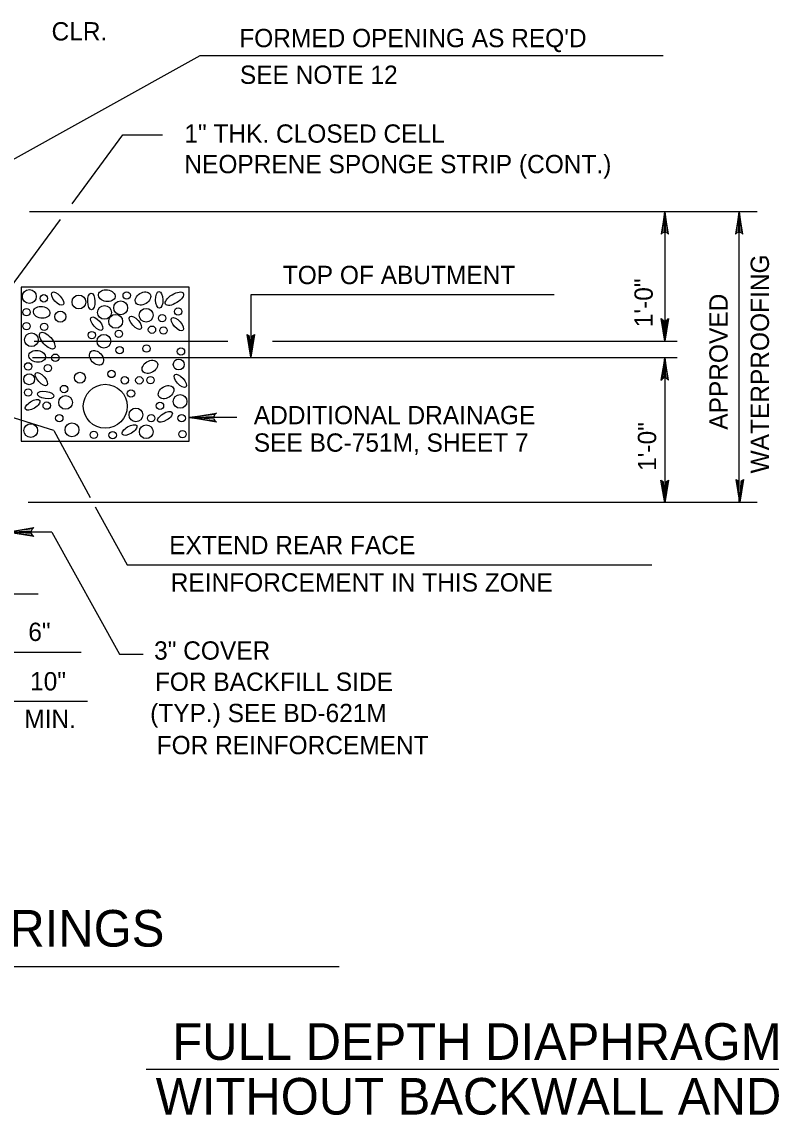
# Model space of a CAD drawing. Extents: x 640009 to 641706, y 298547 to 299735.
# Drawn here: x 640241.3 to 640364.1, y 298840.1 to 299019.2 of the extents above; entities that cross this region are included whole.
import ezdxf

# ---------------------------------------------------------------- set-up
doc = ezdxf.new("R2010")
doc.units = 0
doc.layers.add('1', color=7, linetype='Continuous')

msp = doc.modelspace()

# ---------------------------------------------------------------- linework, layer by layer
at = {"layer": '1'}
for p, q in [((640219.04, 298985.1), (640270.52, 299013.67)), ((640270.52, 299013.67), (640346.41, 299013.67)), ((640249.51, 298989.36), (640257.85, 299000.68)), ((640257.85, 299000.68), (640264.33, 299000.68)), ((640242.54, 298988.1), (640361.79, 298988.1)), ((640346.65, 298988.1), (640346.65, 298966.85)), ((640358.83, 298940.47), (640358.83, 298988.1)), ((640233.17, 298967.22), (640247.62, 298986.81)), ((640328.54, 298974.47), (640278.79, 298974.47)), ((640278.79, 298974.47), (640278.79, 298964.22)), ((640243.29, 298966.85), (640275.01, 298966.85)), ((640282.36, 298966.85), (640348.67, 298966.85)), ((640243.04, 298964.22), (640348.67, 298964.22)), ((640346.65, 298964.22), (640346.65, 298940.47)), ((640246.54, 298952.22), (640234.67, 298955.97)), ((640276.51, 298954.35), (640268.7, 298954.35)), ((640246.54, 298952.22), (640252.46, 298941.25)), ((640242.28, 298940.47), (640361.79, 298940.47)), ((640253.28, 298939.73), (640258.54, 298930.22)), ((640246.18, 298935.6), (640238.79, 298935.6)), ((640246.18, 298935.6), (640257.26, 298915.59)), ((640258.54, 298930.22), (640344.54, 298930.22)), ((640217.42, 298925.47), (640243.92, 298925.47)), ((640251.01, 298915.85), (640226.42, 298915.85)), ((640257.26, 298915.59), (640261.17, 298915.59)), ((640252.04, 298907.85), (640219.29, 298907.85)), ((640161, 298864.4), (640293.29, 298864.4)), ((640261.67, 298847.62), (640460.34, 298847.62))]:
    msp.add_line(p, q, dxfattribs=at)
for points in [[(640347.1, 298984.56), (640346.84, 298984.7), (640346.65, 298988.1), (640347.1, 298984.56), (640347.26, 298984.38), (640346.65, 298988.1), (640346.49, 298984.7), (640346.23, 298984.57), (640346.65, 298988.1), (640346.05, 298984.38), (640346.23, 298984.57)], [(640359.28, 298984.56), (640359.02, 298984.7), (640358.83, 298988.1), (640359.28, 298984.56), (640359.43, 298984.38), (640358.83, 298988.1), (640358.67, 298984.7), (640358.41, 298984.57), (640358.83, 298988.1), (640358.23, 298984.38), (640358.41, 298984.57)], [(640347.1, 298970.39), (640346.84, 298970.24), (640346.65, 298966.85), (640347.1, 298970.39), (640347.26, 298970.56), (640346.65, 298966.85), (640346.49, 298970.24), (640346.23, 298970.37), (640346.65, 298966.85), (640346.05, 298970.56), (640346.23, 298970.37)], [(640279.23, 298967.8), (640278.97, 298967.65), (640278.78, 298964.26), (640279.23, 298967.8), (640279.38, 298967.97), (640278.78, 298964.26), (640278.61, 298967.65), (640278.36, 298967.78), (640278.78, 298964.26), (640278.18, 298967.97), (640278.36, 298967.78)], [(640347.09, 298960.65), (640346.82, 298960.79), (640346.64, 298964.18), (640347.09, 298960.65), (640347.24, 298960.47), (640346.64, 298964.18), (640346.47, 298960.79), (640346.22, 298960.66), (640346.64, 298964.18), (640346.03, 298960.47), (640346.22, 298960.66)], [(640272.95, 298953.81), (640272.77, 298954.12), (640268.7, 298954.35), (640272.95, 298953.81), (640273.16, 298953.62), (640268.7, 298954.35), (640272.77, 298954.54), (640272.93, 298954.85), (640268.7, 298954.35), (640273.16, 298955.07), (640272.93, 298954.85)], [(640347.09, 298943.92), (640346.82, 298943.78), (640346.64, 298940.38), (640347.09, 298943.92), (640347.24, 298944.1), (640346.64, 298940.38), (640346.47, 298943.78), (640346.22, 298943.91), (640346.64, 298940.38), (640346.03, 298944.1), (640346.22, 298943.91)], [(640359.38, 298944.05), (640359.12, 298943.9), (640358.93, 298940.51), (640359.38, 298944.05), (640359.54, 298944.22), (640358.93, 298940.51), (640358.77, 298943.9), (640358.51, 298944.03), (640358.93, 298940.51), (640358.33, 298944.22), (640358.51, 298944.03)], [(640243.04, 298935.07), (640242.86, 298935.38), (640238.79, 298935.6), (640243.04, 298935.07), (640243.25, 298934.88), (640238.79, 298935.6), (640242.86, 298935.8), (640243.02, 298936.11), (640238.79, 298935.6), (640243.25, 298936.33), (640243.02, 298936.11)]]:
    msp.add_lwpolyline(points, dxfattribs=at)
msp.add_lwpolyline([(640268.7, 298975.7), (640241.17, 298975.7), (640241.17, 298950.51), (640268.7, 298950.51)], close=True, dxfattribs=at)
for centre, radius in [((640242.5, 298974.19), 1.13), ((640244.88, 298973.89), 0.605), ((640250.63, 298973.29), 1.13), ((640258.46, 298974.37), 0.605), ((640254.82, 298971.59), 1.13), ((640257.47, 298972.33), 1.13), ((640242.03, 298971.61), 0.605), ((640247.57, 298970.89), 0.9), ((640256.65, 298970.12), 1.13), ((640261.65, 298971.11), 1.13), ((640264.26, 298970.65), 0.605), ((640266.88, 298971.72), 0.605), ((640242.03, 298969.33), 0.605), ((640244.93, 298969.22), 0.605), ((640262.6, 298968.75), 0.605), ((640264.5, 298968.63), 0.605), ((640242.84, 298967.11), 1.13), ((640252.74, 298967.87), 0.605), ((640254.72, 298966.86), 1.13), ((640257.18, 298968.08), 0.605), ((640257.3, 298965.4), 0.605), ((640261.7, 298965.66), 0.605), ((640267.35, 298965.19), 0.605), ((640246.76, 298964.16), 0.605), ((640266.99, 298963.05), 0.9), ((640242.3, 298962.74), 0.605), ((640245.54, 298962.44), 0.605), ((640250.79, 298960.88), 0.9), ((640255.97, 298961.5), 0.605), ((640242.47, 298960.63), 0.9), ((640258.14, 298960.46), 0.605), ((640260.53, 298960.46), 0.605), ((640262.35, 298960.49), 0.605), ((640242.3, 298958.46), 0.605), ((640248.19, 298959.03), 0.605), ((640254.94, 298956.21), 3.6), ((640259.16, 298958.29), 0.605), ((640245.35, 298956.31), 0.605), ((640248.45, 298956.84), 1.13), ((640263.91, 298956.27), 0.605), ((640267.2, 298957), 1.13), ((640247.41, 298954.25), 0.605), ((640259.97, 298954.79), 1.13), ((640262.48, 298954.25), 0.605), ((640267.47, 298954.25), 0.605), ((640242.73, 298952.22), 1.13), ((640249.49, 298952.34), 1.13), ((640261.67, 298952.03), 1.13), ((640253.06, 298951.53), 0.605), ((640256.16, 298951.47), 0.605), ((640267.59, 298951.64), 0.605)]:
    msp.add_circle(centre, radius, dxfattribs=at)
for centre, major_axis, ratio in [((640247.13, 298973.84), (0.91, -1.02), 0.438009), ((640252.66, 298973.39), (0.04, -1.37), 0.438009), ((640255.19, 298974.33), (1.36, -0.2), 0.696126), ((640261.12, 298973.86), (1.17, 0.72), 0.696126), ((640263.79, 298973.63), (0.04, -1.37), 0.438009), ((640266.28, 298973.83), (1.46, 0.9), 0.438009), ((640244.52, 298971.6), (1.36, -0.2), 0.696126), ((640253.55, 298969.74), (0.91, -1.02), 0.438009), ((640259.89, 298969.88), (0.91, -1.02), 0.438009), ((640266.76, 298969.65), (0.91, -1.02), 0.438009), ((640245.44, 298966.96), (1.14, -1.28), 0.438009), ((640243.79, 298964.39), (1.36, -0.2), 0.696126), ((640253.51, 298964.14), (0.91, -1.02), 0.696126), ((640262.26, 298962.68), (1.17, 0.72), 0.696126), ((640244.48, 298960.65), (0.91, -1.02), 0.438009), ((640267.24, 298960.38), (0.91, -1.02), 0.438009), ((640245.17, 298958.05), (1.36, -0.2), 0.438009), ((640264.91, 298958.52), (1.17, 0.72), 0.696126), ((640243.03, 298956.43), (1.17, 0.72), 0.438009), ((640264.73, 298954.47), (1.17, 0.72), 0.438009), ((640258.93, 298952.31), (1.17, 0.72), 0.438009)]:
    msp.add_ellipse(centre, major_axis=major_axis, ratio=ratio, dxfattribs=at)

# ---------------------------------------------------------------- texts
for s, height, p in [('CLR.', 3, (640246.14, 299016.14)), ("FORMED OPENING AS REQ'D", 3, (640276.9, 299015.04)), ('SEE NOTE 12', 3, (640277.01, 299009.03)), ('1" THK. CLOSED CELL', 3, (640267.91, 298999.39)), ('NEOPRENE SPONGE STRIP (CONT.)', 3, (640267.91, 298994.39)), ('TOP OF ABUTMENT', 3, (640284.04, 298976.22)), ('ADDITIONAL DRAINAGE', 3, (640279.29, 298953.26)), ('SEE BC-751M, SHEET 7', 3, (640279.29, 298948.76)), ('EXTEND REAR FACE', 3, (640265.42, 298931.97)), ('REINFORCEMENT IN THIS ZONE', 3, (640265.67, 298925.85)), ('6"', 3, (640242.33, 298917.75)), ('3" COVER', 3, (640262.95, 298914.69)), ('10"', 3, (640242.62, 298909.65)), ('FOR BACKFILL SIDE', 3, (640263.08, 298909.57)), ('MIN.', 3, (640241.67, 298903.48)), ('(TYP.) SEE BD-621M', 3, (640262.3, 298904.45)), ('FOR REINFORCEMENT', 3, (640263.37, 298899.2)), ('SECTION - POT BEARINGS', 6, (640161.66, 298867.67))]:
    msp.add_text(s, height=height, dxfattribs=at).set_placement(p)
for s, height, rotation, p in [('WATERPROOFING', 3, 90, (640363.73, 298945.2)), ('1\'-0"', 3, 90, (640344.68, 298969.16)), ('APPROVED', 3, 90, (640356.96, 298952.36)), ('1\'-0"', 3, 90, (640345.24, 298945.62)), ('FULL DEPTH DIAPHRAGM AT ABUTMENT', 6, 360, (640265.93, 298849.12)), ('WITHOUT BACKWALL AND PAVING NOTCH', 6, 360, (640263.21, 298840.15))]:
    msp.add_text(s, height=height, rotation=rotation, dxfattribs=at).set_placement(p)

doc.saveas('drawing.dxf')
